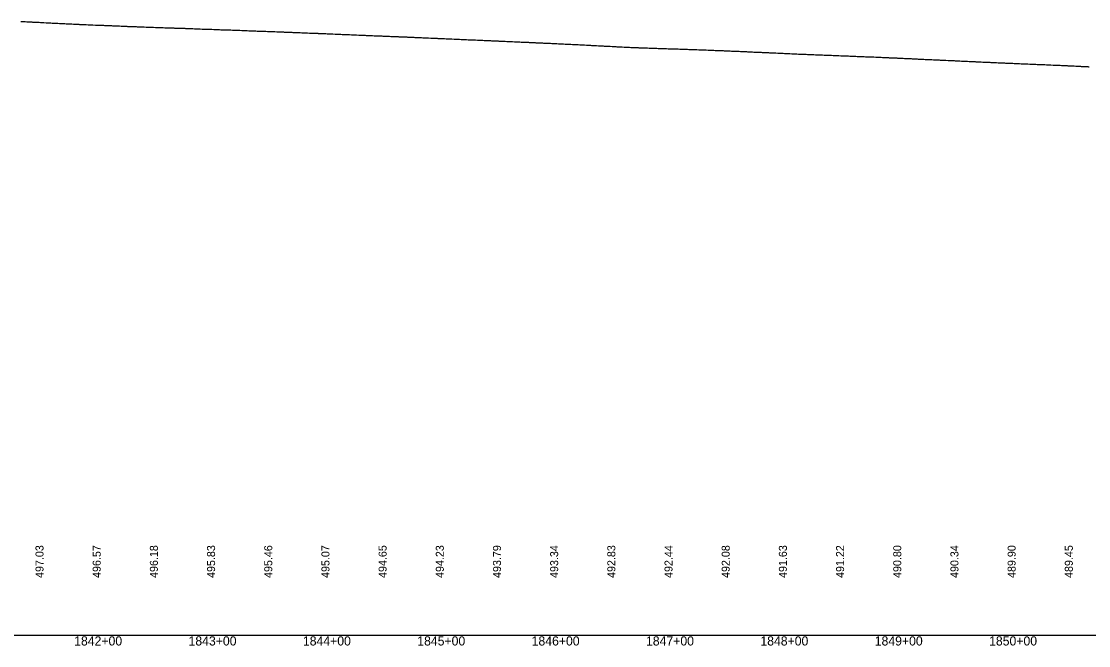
# Model space of a CAD drawing. Extents: x 2017200 to 2047700, y 854850 to 893350.
# Drawn here: x 2039130 to 2040063, y 856091 to 856636 of the extents above; entities that cross this region are included whole.
import ezdxf

# ---------------------------------------------------------------- set-up
doc = ezdxf.new("R2010")
doc.units = 0
for name, color, linetype in [('RD_DDB_Profile_EX', 7, 'Continuous'), ('RD_DDB_StaTX', 7, 'Continuous'), ('RD_DDB_StripGrade', 7, 'Continuous'), ('RD_GPK_Profile_Cell', 7, 'Continuous')]:
    doc.layers.add(name, color=color, linetype=linetype)

msp = doc.modelspace()

# ---------------------------------------------------------------- linework, layer by layer
at = {"layer": 'RD_DDB_Profile_EX'}
msp.add_lwpolyline([(2039129.06, 856636.26), (2039130.95, 856636.16), (2039131.53, 856636.13), (2039132.92, 856636.05), (2039134.4, 856635.96), (2039134.96, 856635.92), (2039135.79, 856635.88), (2039137, 856635.81), (2039138.32, 856635.75), (2039138.74, 856635.71), (2039139.22, 856635.69), (2039141.14, 856635.65), (2039142, 856635.6), (2039143.11, 856635.54), (2039144.64, 856635.47), (2039145.15, 856635.45), (2039146.34, 856635.36), (2039147.19, 856635.32), (2039148.44, 856635.26), (2039149.38, 856635.19), (2039151.33, 856635.09), (2039152.47, 856635.02), (2039153.3, 856634.97), (2039154.87, 856634.88), (2039155.34, 856634.86), (2039156.58, 856634.81), (2039157.38, 856634.79), (2039158.57, 856634.72), (2039159.42, 856634.67), (2039161.1, 856634.6), (2039161.5, 856634.58), (2039162.94, 856634.51), (2039163.63, 856634.47), (2039165.53, 856634.38), (2039166.81, 856634.31), (2039167.57, 856634.28), (2039168.69, 856634.22), (2039169.61, 856634.18), (2039170.23, 856634.13), (2039171.64, 856634.07), (2039173.68, 856633.99), (2039175.34, 856633.92), (2039175.72, 856633.9), (2039176.28, 856633.87), (2039177.76, 856633.79), (2039178.76, 856633.75), (2039179.8, 856633.71), (2039180.46, 856633.66), (2039181.83, 856633.6), (2039183.88, 856633.51), (2039185.58, 856633.45), (2039185.91, 856633.43), (2039186.4, 856633.41), (2039187.95, 856633.34), (2039188.99, 856633.29), (2039189.99, 856633.26), (2039191.46, 856633.19), (2039192.02, 856633.17), (2039194.35, 856633.08), (2039196.1, 856633.03), (2039196.52, 856633.02), (2039198.14, 856632.94), (2039199.05, 856632.91), (2039200.18, 856632.85), (2039201.58, 856632.81), (2039202.24, 856632.77), (2039202.65, 856632.75), (2039204.36, 856632.68), (2039204.82, 856632.66), (2039206.29, 856632.6), (2039207.76, 856632.56), (2039208.33, 856632.54), (2039209.17, 856632.5), (2039210.36, 856632.42), (2039211.7, 856632.39), (2039212.38, 856632.36), (2039212.85, 856632.34), (2039214.6, 856632.28), (2039215.29, 856632.26), (2039216.77, 856632.2), (2039218.52, 856632.11), (2039219.3, 856632.07), (2039220.55, 856632.01), (2039221.83, 856631.96), (2039222.52, 856631.92), (2039223.04, 856631.9), (2039224.82, 856631.86), (2039225.76, 856631.82), (2039226.89, 856631.76), (2039228.71, 856631.68), (2039229.93, 856631.63), (2039230.74, 856631.59), (2039231.95, 856631.55), (2039232.64, 856631.51), (2039233.22, 856631.49), (2039235.03, 856631.45), (2039236.23, 856631.41), (2039237.01, 856631.38), (2039238.89, 856631.3), (2039239.54, 856631.28), (2039240.93, 856631.22), (2039242.07, 856631.18), (2039242.75, 856631.14), (2039243.38, 856631.12), (2039244.88, 856631.08), (2039245.23, 856631.06), (2039247.05, 856631.03), (2039248.7, 856630.97), (2039249.08, 856630.96), (2039249.66, 856630.93), (2039251.12, 856630.87), (2039252.19, 856630.85), (2039252.87, 856630.82), (2039253.52, 856630.8), (2039255.02, 856630.74), (2039255.4, 856630.73), (2039257.25, 856630.68), (2039259.27, 856630.62), (2039260.64, 856630.57), (2039261.31, 856630.55), (2039262.31, 856630.51), (2039262.99, 856630.48), (2039263.66, 856630.46), (2039265.16, 856630.43), (2039265.58, 856630.42), (2039267.64, 856630.35), (2039269.46, 856630.31), (2039270.87, 856630.25), (2039271.5, 856630.23), (2039272.43, 856630.19), (2039273.1, 856630.14), (2039273.8, 856630.12), (2039275.28, 856630.09), (2039275.74, 856630.07), (2039277.65, 856629.99), (2039278.11, 856629.97), (2039279.65, 856629.93), (2039281.11, 856629.86), (2039281.69, 856629.84), (2039282.56, 856629.79), (2039283.73, 856629.73), (2039285.09, 856629.71), (2039285.41, 856629.71), (2039285.89, 856629.69), (2039287.84, 856629.56), (2039288.58, 856629.55), (2039289.84, 856629.51), (2039291.34, 856629.47), (2039291.88, 856629.46), (2039292.68, 856629.42), (2039293.92, 856629.36), (2039295.21, 856629.33), (2039296.04, 856629.3), (2039298.03, 856629.22), (2039299.05, 856629.19), (2039300.03, 856629.16), (2039301.58, 856629.1), (2039302.07, 856629.09), (2039302.8, 856629.06), (2039304.11, 856628.99), (2039305.33, 856628.94), (2039306.19, 856628.92), (2039306.75, 856628.91), (2039308.47, 856628.89), (2039309.52, 856628.85), (2039310.39, 856628.81), (2039312.26, 856628.76), (2039312.92, 856628.74), (2039314.3, 856628.71), (2039315.45, 856628.66), (2039316.32, 856628.62), (2039316.93, 856628.59), (2039318.36, 856628.54), (2039318.68, 856628.53), (2039319.99, 856628.48), (2039320.51, 856628.46), (2039322.45, 856628.37), (2039323.75, 856628.32), (2039324.49, 856628.29), (2039325.57, 856628.23), (2039326.45, 856628.18), (2039327.09, 856628.15), (2039328.51, 856628.1), (2039328.88, 856628.09), (2039330.63, 856628.04), (2039332.64, 856627.96), (2039333.16, 856627.94), (2039334.68, 856627.88), (2039335.69, 856627.84), (2039336.57, 856627.8), (2039337.25, 856627.78), (2039338.65, 856627.73), (2039339.07, 856627.72), (2039340.93, 856627.68), (2039342.83, 856627.59), (2039343.28, 856627.57), (2039344.86, 856627.52), (2039345.82, 856627.48), (2039346.68, 856627.44), (2039347.39, 856627.41), (2039348.79, 856627.35), (2039349.25, 856627.33), (2039351.04, 856627.31), (2039351.4, 856627.29), (2039353.02, 856627.21), (2039353.41, 856627.2), (2039355.05, 856627.12), (2039355.94, 856627.09), (2039356.79, 856627.06), (2039357.54, 856627.03), (2039358.91, 856626.97), (2039359.42, 856626.95), (2039361.26, 856626.9), (2039361.87, 856626.88), (2039363.21, 856626.83), (2039364.69, 856626.76), (2039365.24, 856626.74), (2039366.06, 856626.71), (2039366.89, 856626.67), (2039367.67, 856626.63), (2039369.03, 856626.58), (2039369.59, 856626.56), (2039371.46, 856626.5), (2039372.34, 856626.48), (2039373.4, 856626.44), (2039374.93, 856626.35), (2039375.43, 856626.33), (2039376.18, 856626.3), (2039377.47, 856626.25), (2039377.8, 856626.23), (2039379.14, 856626.19), (2039379.74, 856626.17), (2039381.65, 856626.07), (2039382.81, 856626.05), (2039383.58, 856626.03), (2039385.16, 856625.93), (2039385.62, 856625.92), (2039386.3, 856625.88), (2039387.66, 856625.83), (2039388.83, 856625.81), (2039389.25, 856625.78), (2039389.88, 856625.76), (2039391.49, 856625.7), (2039391.83, 856625.69), (2039393.28, 856625.65), (2039393.77, 856625.63), (2039395.4, 856625.55), (2039395.81, 856625.53), (2039397.11, 856625.44), (2039397.85, 856625.42), (2039398.95, 856625.38), (2039400.02, 856625.33), (2039401.61, 856625.27), (2039401.99, 856625.26), (2039404.01, 856625.19), (2039406, 856625.12), (2039406.54, 856625.09), (2039408.04, 856624.99), (2039409.07, 856624.95), (2039410.15, 856624.9), (2039410.86, 856624.87), (2039412.15, 856624.83), (2039412.59, 856624.81), (2039414.22, 856624.76), (2039415.87, 856624.69), (2039416.19, 856624.67), (2039416.67, 856624.65), (2039418.23, 856624.58), (2039419.2, 856624.54), (2039420.27, 856624.48), (2039421.01, 856624.46), (2039422.3, 856624.42), (2039422.78, 856624.39), (2039424.69, 856624.33), (2039426.38, 856624.25), (2039426.79, 856624.23), (2039428.42, 856624.15), (2039429.32, 856624.12), (2039430.38, 856624.07), (2039431.16, 856624.03), (2039432.43, 856623.99), (2039432.96, 856623.97), (2039434.67, 856623.9), (2039435.17, 856623.88), (2039436.57, 856623.81), (2039438.05, 856623.74), (2039438.61, 856623.72), (2039439.44, 856623.68), (2039440.5, 856623.62), (2039441.3, 856623.59), (2039442.57, 856623.55), (2039443.13, 856623.52), (2039444.89, 856623.48), (2039445.64, 856623.46), (2039447.03, 856623.39), (2039448.8, 856623.31), (2039449.56, 856623.28), (2039450.6, 856623.22), (2039451.43, 856623.19), (2039452.69, 856623.15), (2039453.3, 856623.13), (2039455.1, 856623.05), (2039456.11, 856623.02), (2039457.15, 856622.98), (2039458.99, 856622.9), (2039459.68, 856622.87), (2039460.69, 856622.81), (2039461.56, 856622.78), (2039462.8, 856622.74), (2039463.46, 856622.72), (2039464.96, 856622.67), (2039465.3, 856622.65), (2039466.58, 856622.61), (2039467.27, 856622.57), (2039469.18, 856622.48), (2039469.8, 856622.46), (2039470.79, 856622.4), (2039471.69, 856622.37), (2039472.91, 856622.33), (2039473.6, 856622.3), (2039475.09, 856622.25), (2039475.48, 856622.23), (2039477.33, 856622.15), (2039478.99, 856622.08), (2039479.37, 856622.07), (2039480.69, 856621.98), (2039481.4, 856621.95), (2039481.8, 856621.91), (2039483.02, 856621.87), (2039483.74, 856621.84), (2039485.21, 856621.79), (2039485.65, 856621.77), (2039487.52, 856621.69), (2039489.55, 856621.63), (2039490.05, 856621.61), (2039491.59, 856621.51), (2039492.58, 856621.47), (2039493.12, 856621.44), (2039493.87, 856621.41), (2039495.33, 856621.36), (2039495.81, 856621.34), (2039497.99, 856621.26), (2039499.74, 856621.18), (2039501.16, 856621.1), (2039501.78, 856621.08), (2039502.7, 856621.04), (2039504, 856620.97), (2039505.44, 856620.92), (2039505.97, 856620.89), (2039507.92, 856620.84), (2039508.46, 856620.81), (2039509.93, 856620.73), (2039511.4, 856620.67), (2039511.97, 856620.64), (2039512.82, 856620.61), (2039514.12, 856620.53), (2039515.55, 856620.47), (2039516.11, 856620.45), (2039518.1, 856620.37), (2039518.93, 856620.33), (2039520.41, 856620.26), (2039522.16, 856620.19), (2039522.94, 856620.17), (2039524.23, 856620.1), (2039525.06, 856620.06), (2039526.25, 856620.02), (2039526.85, 856619.99), (2039528.54, 856619.91), (2039529.4, 856619.88), (2039530.31, 856619.84), (2039531.87, 856619.75), (2039532.35, 856619.73), (2039533.06, 856619.69), (2039534.34, 856619.62), (2039535.19, 856619.58), (2039536.38, 856619.53), (2039537.01, 856619.51), (2039538.44, 856619.45), (2039538.75, 856619.44), (2039539.87, 856619.4), (2039540.66, 856619.37), (2039542.54, 856619.27), (2039543.81, 856619.2), (2039544.58, 856619.17), (2039545.33, 856619.15), (2039546.5, 856619.11), (2039547.18, 856619.09), (2039548.58, 856619.02), (2039548.96, 856619), (2039550.69, 856618.94), (2039552.34, 856618.85), (2039552.73, 856618.83), (2039554.05, 856618.78), (2039554.77, 856618.74), (2039555.45, 856618.71), (2039556.63, 856618.66), (2039557.32, 856618.62), (2039558.73, 856618.58), (2039559.14, 856618.56), (2039560.88, 856618.48), (2039562.57, 856618.41), (2039562.92, 856618.39), (2039564.28, 856618.3), (2039564.96, 856618.28), (2039565.57, 856618.26), (2039566.73, 856618.22), (2039567.47, 856618.18), (2039568.86, 856618.13), (2039569.32, 856618.11), (2039571.28, 856618.04), (2039573.11, 856617.95), (2039573.55, 856617.93), (2039575.15, 856617.85), (2039576.08, 856617.81), (2039576.85, 856617.76), (2039577.6, 856617.72), (2039578.99, 856617.67), (2039579.49, 856617.64), (2039581.32, 856617.56), (2039581.75, 856617.55), (2039583.3, 856617.48), (2039584.75, 856617.4), (2039585.34, 856617.37), (2039586.2, 856617.33), (2039586.93, 856617.29), (2039587.74, 856617.25), (2039589.1, 856617.2), (2039589.65, 856617.17), (2039591.53, 856617.1), (2039592.22, 856617.07), (2039593.49, 856617.02), (2039593.79, 856617), (2039595.52, 856616.91), (2039596.32, 856616.88), (2039597.04, 856616.83), (2039597.86, 856616.79), (2039599.21, 856616.73), (2039599.8, 856616.7), (2039601.72, 856616.62), (2039602.69, 856616.6), (2039603.68, 856616.56), (2039605.22, 856616.44), (2039605.71, 856616.42), (2039606.45, 856616.38), (2039607.98, 856616.3), (2039609.31, 856616.25), (2039609.95, 856616.22), (2039611.59, 856616.15), (2039611.9, 856616.14), (2039613.16, 856616.09), (2039614.04, 856616.05), (2039615.9, 856615.94), (2039616.57, 856615.91), (2039618.09, 856615.82), (2039619.4, 856615.76), (2039620.08, 856615.73), (2039621.7, 856615.65), (2039622.07, 856615.63), (2039623.63, 856615.55), (2039624.16, 856615.52), (2039626.09, 856615.42), (2039627.4, 856615.33), (2039628.13, 856615.29), (2039629.22, 856615.25), (2039630.21, 856615.2), (2039630.92, 856615.16), (2039632.22, 856615.11), (2039632.64, 856615.09), (2039634.28, 856614.98), (2039636.28, 856614.88), (2039636.81, 856614.85), (2039638.32, 856614.75), (2039639.34, 856614.7), (2039640.33, 856614.64), (2039641.08, 856614.6), (2039642.37, 856614.55), (2039642.85, 856614.52), (2039644.57, 856614.45), (2039646.16, 856614.37), (2039646.47, 856614.36), (2039646.93, 856614.33), (2039648.51, 856614.23), (2039649.46, 856614.17), (2039650.44, 856614.1), (2039651.24, 856614.07), (2039652.5, 856614.03), (2039653.04, 856614), (2039654.72, 856613.91), (2039655.04, 856613.91), (2039656.66, 856613.85), (2039658.1, 856613.75), (2039658.7, 856613.73), (2039659.49, 856613.69), (2039660.54, 856613.65), (2039661.38, 856613.61), (2039662.63, 856613.56), (2039663.21, 856613.54), (2039664.95, 856613.49), (2039665.51, 856613.47), (2039666.85, 856613.41), (2039668.34, 856613.32), (2039668.89, 856613.29), (2039669.6, 856613.26), (2039670.64, 856613.24), (2039671.51, 856613.2), (2039672.75, 856613.17), (2039673.37, 856613.14), (2039675.17, 856613.09), (2039675.98, 856613.07), (2039677.04, 856613.04), (2039678.57, 856612.95), (2039679.08, 856612.94), (2039679.83, 856612.92), (2039680.74, 856612.88), (2039681.64, 856612.84), (2039682.86, 856612.83), (2039683.53, 856612.81), (2039685.04, 856612.73), (2039685.37, 856612.72), (2039686.45, 856612.7), (2039687.42, 856612.67), (2039689.27, 856612.58), (2039689.95, 856612.56), (2039690.82, 856612.51), (2039691.76, 856612.49), (2039692.95, 856612.44), (2039693.68, 856612.41), (2039695.16, 856612.39), (2039695.56, 856612.38), (2039696.92, 856612.34), (2039697.42, 856612.32), (2039699.04, 856612.24), (2039699.46, 856612.23), (2039700.07, 856612.21), (2039700.88, 856612.19), (2039701.87, 856612.15), (2039703.03, 856612.14), (2039703.82, 856612.12), (2039705.26, 856612.07), (2039705.73, 856612.05), (2039707.66, 856611.99), (2039709.65, 856611.93), (2039710.19, 856611.92), (2039710.95, 856611.87), (2039711.97, 856611.83), (2039713.11, 856611.79), (2039713.94, 856611.76), (2039715.36, 856611.71), (2039715.89, 856611.68), (2039717.86, 856611.62), (2039719.51, 856611.56), (2039719.84, 856611.55), (2039720.31, 856611.54), (2039722.07, 856611.47), (2039723.19, 856611.44), (2039724.06, 856611.41), (2039725.45, 856611.36), (2039726.04, 856611.35), (2039728, 856611.29), (2039728.33, 856611.28), (2039730.03, 856611.2), (2039730.43, 856611.19), (2039732.16, 856611.1), (2039733.25, 856611.06), (2039734.17, 856611.03), (2039735.08, 856610.98), (2039736.17, 856610.95), (2039736.82, 856610.93), (2039738.39, 856610.88), (2039738.8, 856610.87), (2039740.21, 856610.8), (2039740.56, 856610.79), (2039742.25, 856610.72), (2039743.37, 856610.68), (2039744.27, 856610.62), (2039745.22, 856610.58), (2039746.3, 856610.54), (2039747, 856610.52), (2039748.64, 856610.44), (2039749.27, 856610.41), (2039750.68, 856610.34), (2039752.32, 856610.29), (2039753.48, 856610.23), (2039754.36, 856610.2), (2039755.36, 856610.16), (2039756.41, 856610.13), (2039757.17, 856610.1), (2039758.5, 856610.03), (2039758.86, 856610.02), (2039759.74, 856609.96), (2039760.8, 856609.91), (2039762.4, 856609.85), (2039763.57, 856609.8), (2039764.45, 856609.74), (2039765.46, 856609.7), (2039766.52, 856609.67), (2039767.31, 856609.63), (2039768.64, 856609.57), (2039769.07, 856609.55), (2039770.21, 856609.49), (2039770.78, 856609.46), (2039772.4, 856609.37), (2039772.82, 856609.36), (2039773.67, 856609.34), (2039774.53, 856609.31), (2039775.58, 856609.25), (2039776.62, 856609.22), (2039777.46, 856609.19), (2039778.76, 856609.13), (2039779.26, 856609.1), (2039781.04, 856609.02), (2039783.01, 856608.94), (2039783.76, 856608.9), (2039784.6, 856608.84), (2039785.69, 856608.8), (2039786.71, 856608.76), (2039787.6, 856608.73), (2039788.87, 856608.68), (2039789.44, 856608.65), (2039791.16, 856608.57), (2039793.2, 856608.48), (2039793.85, 856608.44), (2039794.67, 856608.41), (2039795.79, 856608.36), (2039796.79, 856608.32), (2039797.72, 856608.27), (2039798.97, 856608.21), (2039799.6, 856608.17), (2039801.62, 856608.09), (2039803.39, 856608), (2039803.82, 856607.98), (2039804.74, 856607.94), (2039805.89, 856607.89), (2039806.87, 856607.85), (2039807.83, 856607.81), (2039809.07, 856607.75), (2039809.75, 856607.71), (2039811.61, 856607.63), (2039812.09, 856607.62), (2039813.58, 856607.56), (2039813.94, 856607.55), (2039814.81, 856607.51), (2039815.97, 856607.46), (2039816.95, 856607.42), (2039817.94, 856607.38), (2039819.16, 856607.33), (2039819.89, 856607.31), (2039821.8, 856607.22), (2039822.56, 856607.19), (2039824.06, 856607.12), (2039826.06, 856607.06), (2039827.03, 856607.03), (2039828.04, 856606.99), (2039829.25, 856606.93), (2039830.02, 856606.9), (2039831.62, 856606.85), (2039831.98, 856606.84), (2039833.03, 856606.79), (2039834.18, 856606.74), (2039836.14, 856606.68), (2039837.12, 856606.66), (2039838.14, 856606.63), (2039839.35, 856606.56), (2039840.14, 856606.53), (2039841.71, 856606.45), (2039842.14, 856606.43), (2039843.5, 856606.38), (2039844.3, 856606.35), (2039846.22, 856606.26), (2039847.43, 856606.21), (2039848.23, 856606.2), (2039849.29, 856606.15), (2039850.25, 856606.1), (2039851.1, 856606.07), (2039852.28, 856606.03), (2039852.78, 856606.01), (2039853.97, 856605.97), (2039854.42, 856605.95), (2039856.37, 856605.87), (2039856.95, 856605.85), (2039858.32, 856605.78), (2039859.41, 856605.75), (2039860.36, 856605.71), (2039861.24, 856605.67), (2039862.42, 856605.62), (2039862.98, 856605.61), (2039864.53, 856605.55), (2039866.22, 856605.47), (2039866.56, 856605.46), (2039867.61, 856605.42), (2039868.4, 856605.39), (2039869.52, 856605.33), (2039870.45, 856605.31), (2039871.39, 856605.3), (2039872.54, 856605.26), (2039873.17, 856605.23), (2039874.91, 856605.15), (2039876.75, 856605.06), (2039877.71, 856605.01), (2039878.46, 856604.97), (2039879.63, 856604.93), (2039880.53, 856604.92), (2039881.52, 856604.87), (2039882.64, 856604.8), (2039883.35, 856604.77), (2039885.03, 856604.72), (2039885.38, 856604.7), (2039886.94, 856604.63), (2039887.79, 856604.57), (2039888.53, 856604.53), (2039889.73, 856604.48), (2039890.61, 856604.45), (2039891.64, 856604.41), (2039892.74, 856604.35), (2039893.51, 856604.32), (2039895.26, 856604.26), (2039895.85, 856604.24), (2039897.13, 856604.18), (2039897.87, 856604.11), (2039898.58, 856604.08), (2039899.82, 856604.03), (2039900.68, 856603.99), (2039901.75, 856603.94), (2039902.83, 856603.91), (2039903.65, 856603.88), (2039905.08, 856603.78), (2039905.46, 856603.76), (2039906.32, 856603.73), (2039907.56, 856603.69), (2039908.65, 856603.64), (2039909.9, 856603.56), (2039910.75, 856603.52), (2039911.85, 856603.48), (2039912.9, 856603.43), (2039913.78, 856603.38), (2039915.18, 856603.32), (2039915.65, 856603.3), (2039916.79, 856603.25), (2039917.68, 856603.21), (2039918.68, 856603.16), (2039919.98, 856603.09), (2039920.8, 856603.05), (2039921.95, 856602.99), (2039922.97, 856602.95), (2039923.9, 856602.92), (2039925.26, 856602.83), (2039925.82, 856602.8), (2039927.26, 856602.72), (2039927.81, 856602.7), (2039930.05, 856602.62), (2039930.85, 856602.58), (2039932.04, 856602.55), (2039933.03, 856602.5), (2039934.01, 856602.45), (2039935.34, 856602.39), (2039935.97, 856602.36), (2039937.93, 856602.23), (2039940.12, 856602.17), (2039940.9, 856602.12), (2039942.12, 856602.05), (2039943.09, 856601.99), (2039944.11, 856601.95), (2039945.4, 856601.93), (2039946.1, 856601.89), (2039948.14, 856601.75), (2039950.18, 856601.67), (2039951.54, 856601.62), (2039952.19, 856601.59), (2039953.43, 856601.53), (2039954.21, 856601.49), (2039955.26, 856601.45), (2039956.23, 856601.42), (2039956.99, 856601.39), (2039958.45, 856601.29), (2039960.24, 856601.23), (2039961.64, 856601.16), (2039962.26, 856601.14), (2039963.55, 856601.07), (2039964.28, 856601.02), (2039965.42, 856600.96), (2039966.33, 856600.92), (2039967.19, 856600.89), (2039968.42, 856600.84), (2039968.74, 856600.83), (2039970.29, 856600.76), (2039971.71, 856600.68), (2039972.32, 856600.67), (2039973.63, 856600.6), (2039974.36, 856600.57), (2039975.51, 856600.52), (2039976.43, 856600.48), (2039977.32, 856600.44), (2039978.56, 856600.42), (2039978.97, 856600.4), (2039979.62, 856600.35), (2039980.69, 856600.28), (2039981.78, 856600.26), (2039982.38, 856600.24), (2039983.71, 856600.17), (2039984.44, 856600.14), (2039985.61, 856600.11), (2039986.52, 856600.06), (2039987.46, 856600), (2039988.68, 856599.95), (2039989.19, 856599.93), (2039990.09, 856599.88), (2039990.87, 856599.84), (2039991.84, 856599.82), (2039992.43, 856599.79), (2039993.79, 856599.76), (2039994.49, 856599.74), (2039995.72, 856599.67), (2039996.59, 856599.62), (2039997.6, 856599.59), (2039998.78, 856599.54), (2039999.38, 856599.51), (2040000.56, 856599.45), (2040001.06, 856599.43), (2040001.9, 856599.42), (2040002.48, 856599.38), (2040003.86, 856599.3), (2040004.56, 856599.28), (2040005.8, 856599.25), (2040006.68, 856599.2), (2040007.71, 856599.14), (2040008.88, 856599.09), (2040009.55, 856599.08), (2040011.31, 856599), (2040012.53, 856598.95), (2040013.93, 856598.91), (2040014.61, 856598.88), (2040015.89, 856598.81), (2040016.73, 856598.76), (2040017.82, 856598.72), (2040018.95, 856598.67), (2040019.71, 856598.63), (2040021.45, 856598.58), (2040022.58, 856598.54), (2040023.99, 856598.48), (2040024.67, 856598.44), (2040025.96, 856598.39), (2040026.81, 856598.35), (2040027.92, 856598.3), (2040029.04, 856598.24), (2040029.84, 856598.21), (2040031.85, 856598.13), (2040034.05, 856598.05), (2040034.73, 856598), (2040036.04, 856597.94), (2040036.88, 856597.89), (2040038.01, 856597.85), (2040039.12, 856597.8), (2040039.97, 856597.76), (2040042.17, 856597.66), (2040044.11, 856597.58), (2040044.78, 856597.53), (2040046.11, 856597.46), (2040046.93, 856597.43), (2040048.1, 856597.37), (2040049.17, 856597.32), (2040050.08, 856597.27), (2040051.65, 856597.2), (2040052.05, 856597.19), (2040052.45, 856597.17), (2040054.17, 856597.07), (2040055.61, 856597), (2040056.17, 856596.96), (2040057.51, 856596.9), (2040058.18, 856596.87), (2040059.36, 856596.81), (2040060.19, 856596.78), (2040061.12, 856596.74), (2040062.2, 856596.69), (2040062.69, 856596.65), (2040063.38, 856596.62)], dxfattribs=at)
at = {"layer": 'RD_GPK_Profile_Cell'}
msp.add_line((2020500, 856100), (2047700, 856100), dxfattribs=at)

# ---------------------------------------------------------------- texts
at = {"layer": 'RD_DDB_StaTX'}
for s, p in [('1842+00', (2039175.8, 856091)), ('1843+00', (2039275.8, 856091)), ('1844+00', (2039375.8, 856091)), ('1845+00', (2039475.8, 856091)), ('1846+00', (2039575.8, 856091)), ('1847+00', (2039675.8, 856091)), ('1848+00', (2039775.8, 856091)), ('1849+00', (2039875.8, 856091)), ('1850+00', (2039975.8, 856091))]:
    msp.add_text(s, height=8, dxfattribs=at).set_placement(p)
at = {"layer": 'RD_DDB_StripGrade'}
for s, p in [('497.03', (2039149, 856150)), ('496.18', (2039249, 856150)), ('495.83', (2039299, 856150)), ('495.46', (2039349, 856150)), ('494.65', (2039449, 856150)), ('494.23', (2039499, 856150)), ('493.34', (2039599, 856150)), ('492.83', (2039649, 856150)), ('492.44', (2039699, 856150)), ('492.08', (2039749, 856150)), ('491.63', (2039799, 856150)), ('490.80', (2039899, 856150)), ('490.34', (2039949, 856150)), ('489.90', (2039999, 856150)), ('489.45', (2040049, 856150)), ('496.57', (2039199, 856150)), ('495.07', (2039399, 856150)), ('493.79', (2039549, 856150)), ('491.22', (2039849, 856150))]:
    msp.add_text(s, height=7, rotation=90, dxfattribs=at).set_placement(p)

doc.saveas('drawing.dxf')
